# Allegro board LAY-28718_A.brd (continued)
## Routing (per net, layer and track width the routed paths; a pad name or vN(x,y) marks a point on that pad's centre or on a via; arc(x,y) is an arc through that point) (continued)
PTD7: length 34.8
  TOP w0.152: J1.3 61.05,48.22 v1(61.05,43.97) ; v1(66.89,19.2) 66.89,18.06 66.64,17.81 65.83,17.81 U13.48
  INT_1 w0.152: v1(66.89,19.2) 66.89,22 66.26,22.63 66.26,24.79 66.51,25.04 66.51,25.43 65.24,26.7 65.24,31.27 64.73,31.78 64.73,40.28 v1(61.05,43.97)
PTE16: length 38.2
  TOP w0.127: U13.3 64.62,21.19 65.11,21.68 65.11,22 65.94,22.82 66.45,22.82
  TOP w0.152: 66.45,22.82 67.59,21.68 67.59,20.41 68.67,19.33 68.67,18.19 71.21,15.65 v1(71.21,12.34) ; 64.62,21.06 U13.3
  INT_1 w0.152: v1(71.21,12.34) 68.41,12.34 62.19,6.12 62.19,4.34 61.68,3.84 54.64,3.84 J4.4
PTE24: length 60.2
  TOP w0.152: v1(56.73,25.49) U13.15 ; v1(44.16,37.62) 44.16,51.71 44.54,52.1 54.64,52.1 J1.8
  INT_1 w0.152: J1.1 62.26,49.56 57.56,49.56 56.29,50.83 J1.8 ; v1(56.73,25.49) 56.1,26.12 56.1,32.28 55.33,33.05 55.33,34.82 52.54,37.62 v1(44.16,37.62)
PTE25: length 75.8
  TOP w0.152: v1(71.72,17.42) 72.86,16.28 77.43,16.28 R73.2 ; v1(44.67,37.11) 44.67,49.17 45.05,49.56 49.56,49.56 J1.12 ; v1(56.73,24.79) 56.73,24.78 U13.16 60.54,20.97 60.54,19.2 61.94,17.81 v1(61.94,17.42)
  INT_1 w0.152: v1(44.67,37.11) 52.03,37.11 54.32,34.82 54.32,33.43 55.71,32.03 55.71,25.81 v1(56.73,24.79) ; J1.12 52.1,49.56 56.86,49.56 58.13,48.29 J1.5
  BOTTOM w0.152: v1(71.72,17.42) v1(61.94,17.42)
PTE29: length 62.8
  TOP w0.152: J1.13 47.08,47.08 v1(47.08,41.81) ; U13.13 61.3,22.33 61.3,19.96 v1(63.33,17.93) ; v1(72.8,17.04) R74.2
  INT_1 w0.152: v1(47.08,41.81) 50.51,41.81 51.9,40.41 55.46,40.41 60.67,35.2 60.67,24.03 61.3,23.39 61.3,19.96 v1(63.33,17.93) ; J1.14 J1.13
  BOTTOM w0.152: v1(63.33,17.93) 71.91,17.93 v1(72.8,17.04)
RST_TGTMCU_B: length 121.2
  TOP w0.152: 35.78,29.62 35.78,29.68 35.46,30 33.49,30 J25.3 ; 35.78,29.62 36.16,30 D1.C ; 35.78,29.62 R10.2 v1(36.54,28.47) ; v1(40.35,24.16) R11.2 39.84,25.43 U3.7 ; v1(58.25,19.46) 57.37,19.46 57.37,19.46 U13.26 54.44,16.54 54.19,16.54 51.9,14.25 51.9,13.49 v1(51.78,13.36) ; v1(58.76,34.82) 72.86,34.82 73.37,35.33 73.37,39.27 73.75,39.65 J9.10
  INT_1 w0.152: J3.6 31.65,3.9 27.2,3.9 26.76,4.34 26.76,9.55 34.51,17.3 34.51,28.98 J25.3 ; v1(51.78,13.36) 42,13.36 40.35,15.01 v1(40.35,24.16) 40.35,25.55 39.78,26.12 37.11,26.12 36.54,26.7 v1(36.54,28.47) ; v1(58.25,19.46) 58.25,26.57 57.75,27.08 57.75,32.92 58.25,33.43 58.25,34.32 v1(58.76,34.82)
SDA_EXTAL: length 7.1
  TOP w0.152: U5.17 20.41,30.7 20.41,29.24 20.15,28.98 18.76,28.98 v1(18.25,28.47) C9.1 18.57,27.39 Y1.3
SDA_JTAG_TCLK: length 14.7
  TOP w0.152: U5.12 17.2,31.58 v1(9.8,31.58)
  INT_1 w0.152: J10.4 9.49,26.7 9.8,27.01 v1(9.8,31.58)
SDA_JTAG_TDI: length 17
  TOP w0.152: U5.13 17.4,31.08 v1(10.31,31.08)
  INT_1 w0.152: J10.8 9.8,24.16 10.31,24.66 v1(10.31,31.08)
SDA_JTAG_TDO: length 16
  TOP w0.152: v1(10.88,25.43) J10.6 ; v1(10.88,30.57) 17.6,30.57 U5.14
  INT_1 w0.152: v1(10.88,30.57) v1(10.88,25.43)
SDA_JTAG_TMS: length 13.3
  TOP w0.152: J10.2 8.09,28.09 R21.2 8.41,30.06 17.8,30.06 U5.15
SDA_LED: length 23.6
  TOP w0.152: D2.C v1(5.3,42) ; v1(22.38,36.92) 22.38,36.76 U5.29
  INT_1 w0.152: v1(5.3,42) 12.09,42 12.92,41.17 20.66,41.17 21.3,40.54 21.3,38 v1(22.38,36.92)
SDA_LED_R: length 2
  TOP w0.152: R17.2 3.28,44.74 v1(4.34,44.74) D2.A
SDA_RST: length 23.6
  TOP w0.152: R5.2 R6.1 ; R6.1 22,29.55 v1(22,28.16) ; R6.1 21.42,30.12 21.42,31.01 20.94,31.5 U5.19
  INT_1 w0.152: v1(22,28.16) 21.55,27.71 14.25,27.71 13.23,26.7 13.23,23.77 12.34,22.89 J10.10
  BOTTOM w0.152: v1(22,28.16) TP5.1
SDA_RST_LED: length 2.3
  TOP w0.152: D1.A R2.2 v1(40.35,30.76)
SDA_RST_TGTMCU_B: length 7.7
  TOP w0.152: v1(22.19,31.65) 22.25,31.65 22.25,31.68 U5.21
  INT_1 w0.152: J5.2 26.25,30.89 22.95,30.89 v1(22.19,31.65)
SDA_RST_TGTMCU_J_B: length 11.8
  TOP w0.152: R14.2 33.49,25.93 J25.1 31.71,26.7 J5.1 ; R14.2 R10.1 ; R14.2 36.98,25.93 37.09,25.83 U3.2
SDA_RX_EN: length 2.4
  TOP w0.152: R23.2 R16.1 U7.5
SDA_SPI0_CS: length 3.8
  TOP w0.152: R3.2 v1(23.96,32.66) 22.69,32.66 U5.23
  BOTTOM w0.152: v1(23.96,32.66) TP1.1
SDA_SPI0_RST_B: length 3.4
  TOP w0.152: U5.22 22.95,31.69 v1(22.95,31.65) R18.2
  BOTTOM w0.152: v1(22.95,31.65) TP6.1
SDA_SPI0_SCK: length 12.4
  TOP w0.152: U2.3 31.2,33.82 30.7,34.32 v1(30.7,35.65) 29.36,35.65 28.85,36.16 23.89,36.16 U5.26
SDA_SPI0_SIN: length 6.4
  TOP w0.152: U5.28 22.35,36.03 v1(22.38,36.03) ; U10.5 25.62,34.82 25.49,34.95 v1(23.46,34.95)
  INT_1 w0.152: v1(23.46,34.95) v1(22.38,36.03)
SDA_SPI0_SOUT: length 12.4
  TOP w0.152: U5.27 22.55,35.52 22.63,35.52 23.71,36.6 29.04,36.6 29.49,36.16 v1(32.35,36.16) U12.3
SDA_SWD_EN: length 31.9
  TOP w0.152: U9.6 12.66,26.7 v1(12.66,25.93) ; R19.1 v1(36.54,33.3) ; R18.1 v1(24.73,29.87) 25.62,29.87 25.81,30.06 v1(25.81,32.09)
  INT_1 w0.152: v1(24.73,29.87) 21.35,29.87 21.12,30.1 20.72,30.1 20.49,29.87 19.14,29.87 18.22,28.96 18.05,28.96 17.77,28.67 17.77,28.5 17.42,28.16 13.61,28.16 12.66,27.2 v1(12.66,25.93) ; v1(25.81,32.09) 29.36,32.09 31.08,33.81 32.22,33.81 32.73,33.3 v1(36.54,33.3)
SDA_SWD_EN_B: length 6.1
  TOP w0.152: R25.2 v1(17.11,26.7) 17.61,27.2 17.61,29.3 18.76,30.44 18.89,30.44 U5.16
SDA_SWD_EN_B_R: length 3.8
  TOP w0.152: v1(15.2,24.92) R26.2 R25.1 15.45,26.7 U9.1
SDA_SWD_EN_R: length 3.7
  TOP w0.152: U2.5 R13.1 ; R13.1 R12.2 ; R13.1 R19.2
SDA_SWD_OE: length 32.5
  TOP w0.152: R33.1 v1(36.54,36.86) ; U9.4 12.66,27.71 v1(12.66,28.73) ; v1(25.23,33.05) 25.23,31.44 R3.1 25.23,31.39 v1(25.23,30.38)
  INT_1 w0.152: v1(12.66,28.73) 17.23,28.73 18.88,30.38 20.56,30.38 20.59,30.4 21.24,30.4 21.27,30.38 v1(25.23,30.38) ; v1(25.23,33.05) 26.89,33.05 27.65,33.81 29.93,33.81 30.19,34.06 30.19,36.47 31.08,37.36 32.79,37.36 33.3,36.86 v1(36.54,36.86)
SDA_SWD_OE_B: length 9.2
  TOP w0.152: v1(22.19,30.89) 21.68,31.39 21.68,31.55 21.3,31.93 U5.20 ; v1(17.11,29.49) 17.11,28.6 R28.2
  INT_1 w0.152: v1(22.19,30.89) 18.5,30.89 v1(17.11,29.49)
SDA_SWD_OE_B_R: length 3.8
  TOP w0.152: v1(15.2,29.49) R27.1 R28.1 15.45,27.7 U9.3
SDA_SWD_OE_R: length 3.7
  TOP w0.152: R39.1 R33.2 ; R39.1 R37.2 ; R39.1 U12.5
SDA_USB_CONN_DN: length 16.2
  TOP w0.152: R22.1 15.86,37.98 v1(15.39,38.44) ; J6.2 5.01,35.67 5.17,35.51 6.34,35.51 U4.1 7.52,35.51 8.87,35.51 9.23,35.87 v1(9.23,36.03)
  INT_1 w0.132: v1(9.23,36.03) 9.74,35.52 10.21,35.52 11.93,37.24 15.78,37.24 16.1,37.57 16.1,38.07 15.73,38.44 v1(15.39,38.44)
SDA_USB_CONN_DP: length 16.8
  TOP w0.152: v1(15.96,38.95) 16.43,38.48 R20.1 ; J6.3 5.01,35.02 5.17,35.18 6.33,35.18 U6.1 7.52,35.16 8.92,35.16 9.23,34.85 v1(9.23,34.7)
  INT_1 w0.132: v1(15.96,38.95) 15.96,38.65 16.41,38.2 16.41,37.44 15.91,36.93 12.06,36.93 10.34,35.21 9.74,35.21 v1(9.23,34.7)
SDA_USB_DN: length 2.3
  TOP w0.152: R22.2 17.05,37 18.03,36.03 18.03,35.91 U5.4
SDA_USB_DP: length 2.3
  TOP w0.152: U5.3 18.38,36.27 18.26,36.27 17.34,37.19 R20.2
SDA_USB_P5V_SENSE: length 4.7
  TOP w0.152: R8.2 21.81,37.11 21.81,36.9 U5.30 ; R8.2 R7.1 ; R8.2 22.46,38.99 v1(22.44,39.01)
SDA_USBSHIELD: length 26.2
  TOP w0.508: J6.S3 2.76,39.19 ; J6.S4 2.76,30.84 ; 4.48,31.93 J6.S2 L1.1 ; J6.S1 4.48,38.11
  INT_1 w0.508: J6.S3 2.76,39.19 ; J6.S3 1.48,38.31 ; J6.S3 1.48,40.07 ; 4.48,31.93 J6.S2 5.51,32.79 ; J6.S4 1.48,31.72
  BOTTOM w0.508: J6.S4 2.76,30.84 ; J6.S4 1.48,29.96 ; J6.S4 1.48,31.72 ; 4.48,31.93 J6.S2 ; J6.S2 4.48,33.66 ; J6.S2 5.51,32.79 ; J6.S2 3.45,32.79 ; J6.S3 2.76,39.19 ; J6.S3 1.48,40.07 ; J6.S3 1.48,38.31 ; 3.45,37.24 J6.S1 ; J6.S1 5.51,37.24 ; J6.S1 4.48,38.11 ; J6.S1 4.48,36.38
SDA_VOUT33: length 8.8
  TOP w0.254: U5.5 17.36,35.87 v1(17.36,35.97)
  TOP w0.508: v1(17.36,35.97) 17.06,36.27 15.69,36.27 15.49,36.07 C11.1 ; R36.2 v2(14.12,33.36)
  INT_1 w0.508: v2(14.12,33.36) 14.12,34.44 15.65,35.97 v1(17.36,35.97)
SDA_XTAL: length 6
  TOP w0.152: Y1.1 20.97,27.39 C6.1 20.92,28.09 v1(20.92,29.62) 20.92,30.9 U5.18
SW1_RST_B: length 39.7
  TOP w0.152: SW1.2 9.36,49.31 C2.1 v1(10.19,47.02)
  INT_1 w0.152: J25.2 29.36,31.58 25.23,31.58 24.73,32.09 24.73,35.33 23.2,36.86 23.2,41.68 22.06,42.82 12.92,42.82 10.19,45.55 v1(10.19,47.02)
SWD_CLK_KV10: length 18.1
  TOP w0.152: U13.17 56.73,24.07 v1(56.73,24.09) ; J11.1 49.36,33.17 v1(53.81,33.17)
  INT_1 w0.152: v1(53.81,33.17) 55.21,31.78 55.21,25.62 v1(56.73,24.09)
SWD_CLK_TGTMCU: length 38.6
  TOP w0.152: v1(73.37,33.17) 58.38,33.17 57.75,32.54 46.32,32.54 45.68,33.17 J11.2 J8.2
  INT_1 w0.152: J9.4 73.88,35.84 73.37,35.33 v1(73.37,33.17)
SWD_CLK_TGTMCU_BUF: length 5.2
  TOP w0.152: v1(33.81,33.81) 33.8,33.82 U2.4
  INT_1 w0.152: v1(33.81,33.81) 37.55,33.81 J8.1
SWD_DIO_TGTMCU: length 56.1
  TOP w0.152: U13.20 56.91,21.74 58.06,20.6 58.32,20.6 59.27,19.65 v1(59.27,19.46) ; J9.2 74.89,34.32 v1(59.27,34.32) 58.51,34.32 57.18,32.98 54.95,32.98 54.25,33.68 51.9,33.68 50,35.59 42.89,35.59 J12.2
  INT_1 w0.152: v1(59.27,34.32) 59.27,33.3 58.64,32.66 58.64,27.33 59.27,26.7 v1(59.27,19.46)
SWD_DIO_TGTMCU_BUF: length 14.4
  TOP w0.152: U12.4 33.8,37.37 v1(33.81,37.36) ; U10.2 v1(29.68,34.32)
  INT_1 w0.152: v1(29.68,34.32) 29.68,37.36 30.7,38.38 32.79,38.38 v1(33.81,37.36) 37.55,37.36 J12.1
TC_EXTAL_TP: length 2.9
  TOP w0.152: U5.10 16.8,32.6 v1(16.47,32.6)
  BOTTOM w0.152: TP9.1 15.46,31.58 v1(16.47,32.6)
TC_SDA_USB_ID_TP: length 2.5
  TOP w0.152: v1(5.42,34.44) 4.15,34.44 J6.4
  BOTTOM w0.152: TP7.1 v1(5.42,34.44)
TC_XTAL_TP: length 3.1
  TOP w0.152: U5.9 16.75,33.35 16.51,33.11 v1(15.96,33.11)
  BOTTOM w0.152: v1(15.96,33.11) 15.14,32.28 TP10.1
THER_A: length 4.9
  TOP w0.152: R45.2 RT1.1 77.94,25.17 C21.1 R47.2 v1(75.65,24.41)
THER_B: length 4.9
  TOP w0.152: R44.1 RT1.2 77.94,26.19 C21.2 R46.2 v1(75.65,26.95)
TP_2102_A: length 1.8
  TOP w0.152: v1(36.47,25.43) U3.3
  BOTTOM w0.152: TP3.1 v1(36.47,25.43)
TP_2102_B: length 1.6
  TOP w0.152: v1(38.76,24.47) 38.76,25.03 U3.6
  BOTTOM w0.152: v1(38.76,24.47) 38.82,24.47 TP2.1
UART0_RX_TGTMCU: length 78.6
  TOP w0.152: J1.6 56.79,52.48 44.28,52.48 43.65,51.84 v1(43.65,36.6) ; R24.2 v1(31.46,36.86) ; R54.2 v1(54.44,12.34)
  INT_1 w0.152: v1(31.46,36.86) 31.91,36.4 32.15,36.64 32.55,36.64 32.83,36.36 32.83,36.35 43.4,36.35 v1(43.65,36.6) 51.65,36.6 52.92,35.33 52.92,20.85 53.94,19.84 53.94,13.74 54.44,13.23 v1(54.44,12.34)
UART0_TX_TGTMCU: length 46.5
  TOP w0.152: v1(56.98,13.36) R55.1 ; R38.2 v1(31.46,33.3)
  INT_1 w0.152: v1(31.46,33.3) 31.97,32.79 33.87,32.79 35.01,31.65 35.01,14.63 37.05,12.6 52.67,12.6 53.43,11.84 54.7,11.84 56.22,13.36 v1(56.98,13.36)
UART1_RX_TGTMCU_BUF: length 1.6
  TOP w0.152: R24.1 29.16,37.37 U7.4
UART1_RX_TGTMCU_R: length 7.8
  TOP w0.152: U7.3 25.43,37.37 v1(25.23,37.17) ; U5.25 22.71,34.32 22.77,34.38 v1(25.23,34.38)
  INT_1 w0.152: v1(25.23,37.17) v1(25.23,34.38)
UART1_TX_TGTMCU_BUF: length 1.4
  TOP w0.152: U10.1 29.19,33.79 R38.1
UART1_TX_TGTMCU_R: length 5.2
  TOP w0.152: U5.24 22.71,33.35 23.01,33.05 23.33,33.05 v1(23.96,33.68) 25.49,33.68 26.12,34.32 U10.6
V_TGTMCU: length 7.6
  TOP w0.203: U3.8 38.82,25.83 v1(38.82,26.7)
  TOP w0.254: v1(33.81,38.89) 33.81,38.57 33.61,38.37 U12.6 ; U10.8 v1(27.9,33.05) ; U2.6 33.61,34.82 v1(33.81,35.01) ; U7.6 28.66,38.37 28.92,38.63 v1(28.92,38.89)
  TOP w0.508: R11.1 v1(40.35,26.7) C23.1 ; R2.1 v1(42.13,30) ; C7.1 v1(38.82,26.7)
VREFH: length 14.6
  TOP w0.203: v1(63.02,24.28) 62.89,24.28 U13.10
  TOP w0.508: v1(63.02,24.28) 63.55,24.81 C29.1 ; L9.1 60.12,30.76 C42.1 C43.1 v1(64.22,30.76) R53.1
  BOTTOM w0.381: v1(63.02,24.28) 64.86,26.12 64.86,28.85 64.95,28.94 64.95,29.54 64.86,29.62 64.86,30.12 v1(64.22,30.76)
VREFL: length 11.6
  TOP w0.203: v1(62.32,24.98) 62.45,24.85 62.45,24.54 U13.11
  TOP w0.508: C29.2 62.85,25.51 v1(62.32,24.98) ; L10.1 60.12,29.24 C42.2 C43.2 v1(64.22,29.24)
  BOTTOM w0.381: v1(64.22,29.24) 64.22,26.89 v1(62.32,24.98)
VTRG_EN: length 5.2
  TOP w0.254: U11.3 12.09,43.08 12.47,43.46 R34.2 R30.1 v1(15.96,43.46) R29.2
VTRG_FAULT_B: length 15.8
  TOP w0.152: U11.4 12.09,45.49 R35.2 v1(14.5,45.49) 16.73,45.49 21.04,41.17 21.04,37.55 U5.32
N20314503: length 4.9
  TOP w0.152: v1(55.84,33.49) R42.1 R64.1 55.83,35.34 U8.16
N20662233: length 4.4
  TOP w0.381: C19.2 9.17,44.73 9.99,43.9 v1(11.14,43.9) U11.5
N20923344: length 2.9
  TOP w0.152: v1(79.02,14) R88.2 76.66,14 D4.2
N21117280: length 11.4
  TOP w0.152: U13.24 55.24,20.09 v1(52.92,20.09) R52.1 C24.2 48.22,21.62 QZ1.2
N21117910: length 10.4
  TOP w0.152: U13.25 55.24,18.57 v1(52.92,18.57) R52.2 C20.2 48.22,17.04 QZ1.1
N21118289: length 5.4
  TOP w0.127: U13.32 56.86,14.71 56.86,14 55.74,12.87 R55.2
  TOP w0.152: R55.2 v1(55.21,11.58)
N21118309: length 3.4
  TOP w0.127: 57.62,16.18 56.22,14.78 v1(56.22,14.12)
  TOP w0.152: R54.1 v1(56.22,14.12)
N21120929: length 3.2
  TOP w0.152: U13.41 62.9,15.83 v1(63.84,14.88) R58.2
N21120946: length 5.2
  TOP w0.127: 63.21,16.18 64.06,15.33 64.16,15.33 65.85,13.64 R59.1
  TOP w0.152: v1(67.14,13.11) R59.1
N21121221: length 5.6
  TOP w0.127: R66.2 53.96,14.65 54.95,15.65 56.38,15.65 57.27,16.54
  TOP w0.152: R66.2 v1(53.43,13.36)
N21128407: length 3.6
  TOP w0.127: v1(54.44,15.9) 54.57,16.03 56.05,16.03 U13.29
  TOP w0.152: R65.1 v1(54.44,15.9)
N21239718: length 1.3
  TOP w0.889: C51.2 R48.1

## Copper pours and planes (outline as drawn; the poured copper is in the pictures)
GND on TOP, GND, INT_1: 0.51,46.99 2.22,51.12 6.35,52.83 74.93,52.83 79.06,51.12 80.77,46.99 80.77,6.35 79.06,2.22 74.93,0.51 6.35,0.51 2.22,2.22 0.51,6.35
P3V3 on BOTTOM: 74.93,52.83 79.06,51.12 80.77,46.99 80.77,6.35 79.06,2.22 74.93,0.51 6.35,0.51 2.22,2.22 0.51,6.35 0.51,23.39 34.44,23.39 34.44,15.9 39.71,15.9 39.71,24.73 42.7,24.73 42.7,24.35 43.84,24.35 43.84,52.83
P3V3_KV10 on BOTTOM: 42,23.14 68.54,23.14 68.54,19.08 42,19.08
P3V3_SDA on BOTTOM: 0.51,46.99 2.22,51.12 6.35,52.83 74.93,52.83 79.06,51.12 80.77,46.99 80.77,6.35 79.06,2.22 74.93,0.51 6.35,0.51 2.22,2.22 0.51,6.35
P5V_SDA on BOTTOM: 21.17,40.73 15.84,40.73 15.84,34 13.36,34 13.36,37.17 9.68,37.17 9.68,43.78 25.11,43.78 25.11,28.35 21.17,28.35
SDA_USBSHIELD on TOP, BOTTOM, INT_1: 0.51,29.24 0.51,40.92 5.8,40.92 5.8,29.24
V_TGTMCU on BOTTOM: 27.39,32.6 27.39,43.78 43.59,43.78 43.59,24.98 38.57,24.98 38.57,40.22 35.14,40.22 35.14,32.6 32.85,32.6 32.85,40.22 29.49,40.22 29.49,32.6

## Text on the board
BOTTOM: 7 OF 10 | SECONDARY SIDE
Ref Des/Assembly Bottom: 2 OF 2 | SECONDARY ASSEMBLY
Board Geometry/Soldermask Bottom: 8 OF 10 | SECONDARY SOLDERMASK
Ref Des/Silkscreen Bottom: NC | A2 | P3V3 | A1 | RST | D5 | D4 | C4 | 5V_USB | ADC0_SE9 | C3 | GND | C2 | ADC0_SE6 | C1 | 5-9Vin | ADC0_DP0 | C0 | ADC0_DM0 | E16 | ADC1_SE2 | ADC0_SE10 | C5 | B3 | DAC0_OUT | B2 | REV A | SCH-28718 | 700-28718 | MANFACTURED IN PRC | CAN ICES-3 (B)/NMB-3(B) | D30 | JACK | 5V PWR | D2 | AREF | C6 | D3 | ADC0_SE4 | ADC0_SE5 | D6 | ADC0_SE7 | A4 | C7 | F29 | E29 | B0 | E25 | D1 | D0 | E24 | B16 | D7 | J2 | J3 | J4 | J1 | 9 OF 10 | SECONDARY SILKSCREEN
User.Comments: 1 OF 1 | TEST PROBE | 1/1 | 1
TOP: 4 OF 10 | PRIMARY SIDE
Ref Des/Assembly Top: 1 OF 2 | PRIMARY ASSEMBLY
Board Geometry/Soldermask Top: 3 OF 10 | PRIMARY SOLDERMASK
Ref Des/Silkscreen Top: SDA | USB | RESET | PWR 5V | RGB | 2 OF 10 | FRDM-KV10Z | PRIMARY SILKSCREEN
GND: 5 OF 10 | GROUND PLANE
INT_1: 6 OF 10 | INTERNAL 1
DIMENSION: GRID ORIGIN | PRIMARY DATUM
BODY_CENTER: 22. . | INTENTIONAL SHORT IN SH1 BETWEEN NETS P3V3 AND V_TGTMCU. | INTENTIONAL SHORT IN J5 BETWEEN NETS SDA_RST_TGTMCU_B AND SDA_RST_TGTMCU_J_B | INTENTIONAL SHORT IN J8 BETWEEN NETS SWD_CLK_TGTMCU_BUF AND SWD_CLK_TGTMCU. | INTENTIONAL SHORT IN J19 BETWEEN P3V3 AND P3V3_REG. | INTENTIONAL SHORT IN J20 BETWEEN P3V3 AND P3V3_KV10. | INTENTIONAL SHORT IN J11 BETWEEN NETS SWD CLK_TGTMCUU AND SWD_CLK_KV10. | INTENTIONAL SHORT IN J12 NETS SWD_DIO_TGTMCU_BUF AND SWD_DIO_TGTMCU. | Prepreg 4.20 mils | Prepreg 45.0 mils | Core 6.00 mils | Theoretically Thickness 63mils
PASTEMASK_TOP: 1 OF 10 | PASTEMASK TOP
User.5: 10 OF 10 | SECONDARY PASTEMASK
User.10: 170-28718 REV A
User.14: P. SUSTEK | 09/04/15 | B | C | D | E
User.17: Int_1 | TOP | layers | Trace spac | 6 | (mils) | Single ended | Impedance | 54 +/-10 | 52 +/-10 | (Ohms) | Trace Width | 6.00 | 5.20 | Differential(USB all nets) | Trace spacing | 7.00 mils | 90 +/-10
User.20: FIGURE | SIZE | 10.0 | 12.0 | 31.0 | 40.0 | 28.0 | 63.0 | 125.0 | 34.0x30.0 | 59.0x33.0 | 91.0x32.0 | 111.0x32.0 | DRILL CHART: TOP to BOTTOM | ALL UNITS ARE IN MILS | TOLERANCE | +2.0/-10.0 | +2.0/-12.0 | +2.0/-2.0 | +3.0/-3.0 | PLATED | NON-PLATED | QTY | 516 | 52 | 20 | 85 | 6 | 2 | 4 | 1
